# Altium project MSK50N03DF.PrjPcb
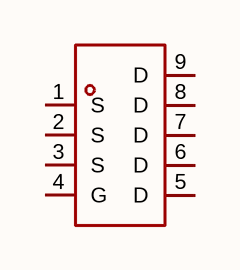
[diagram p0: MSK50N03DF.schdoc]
1 sheet, 1 parts. Net scope: global (net labels, ports and power ports of the same name join across sheets).

## Sheet MSK50N03DF.schdoc
size 127 x 101 mm

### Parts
Q?  msk50n03df  [DFN-8_L3.0-W3.0-P0.65-BL]  (value not drawn)

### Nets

Not connected (* = marked no-connect by the designer): Q? 1(S) 2(S) 3(S) 4(G) 5(D) 6(D) 7(D) 8(D) 9(D)

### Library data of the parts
Q? = msk50n03df: 数量:1个N沟道;漏源电压(Vdss):30V;连续漏极电流(Id):50A;导通电阻(RDS(on)):7.5mΩ@10V；11mΩ@4.5V;耗散功率(Pd):37.5W;阈值电压(Vgs(th)):2.5V;; Manufacturer: MSKSEMI(美森科); AddInBom: yes; ModelId: 8b850663669847e9b39b8fc804d68d4b; ModelName: DFN-8_L3.0-W3.0-H0.7-P0.65; ModelTransform: 118.8974,118.11,0,90,0,0,0,0,0; Number: 1个N沟道; Drain to Source Voltage: 30V; Current - Continuous Drain(Id): 50A; Pd - Power Dissipation: 37.5W; Gate Threshold Voltage (Vgs(th)): 2.5V; Gate Charge(Qg): 9.8nC@4.5V; Input Capacitance(Ciss): 940pF; Reverse Transfer Capacitance (Crss@Vds): 109pF; Type: N沟道; Output Capacitance(Coss): 131pF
